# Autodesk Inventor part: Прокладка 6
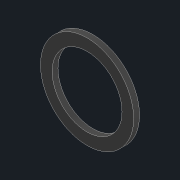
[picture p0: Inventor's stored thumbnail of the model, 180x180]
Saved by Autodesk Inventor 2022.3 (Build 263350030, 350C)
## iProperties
Created: 2022-08
Part Number: Прокладка 6
Material: Резина
Document SubType Name: Modeling
Designer: Карташов
Density: 0.93 g/cm^3
Appearance: Резина — черная
Author: Карташов
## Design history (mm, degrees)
sketch "Эскиз1"
  geometry: C1 r 8 at (8.001, 0) reference; C2 r 6 at (8.001, 0) reference; 1 further point
extrude "Выдавливание1" new body sketch "Эскиз1" distance "d0" = 1; taper "d1" = 0 deg
node "Твердое тело1"
node "Ссылка1"
